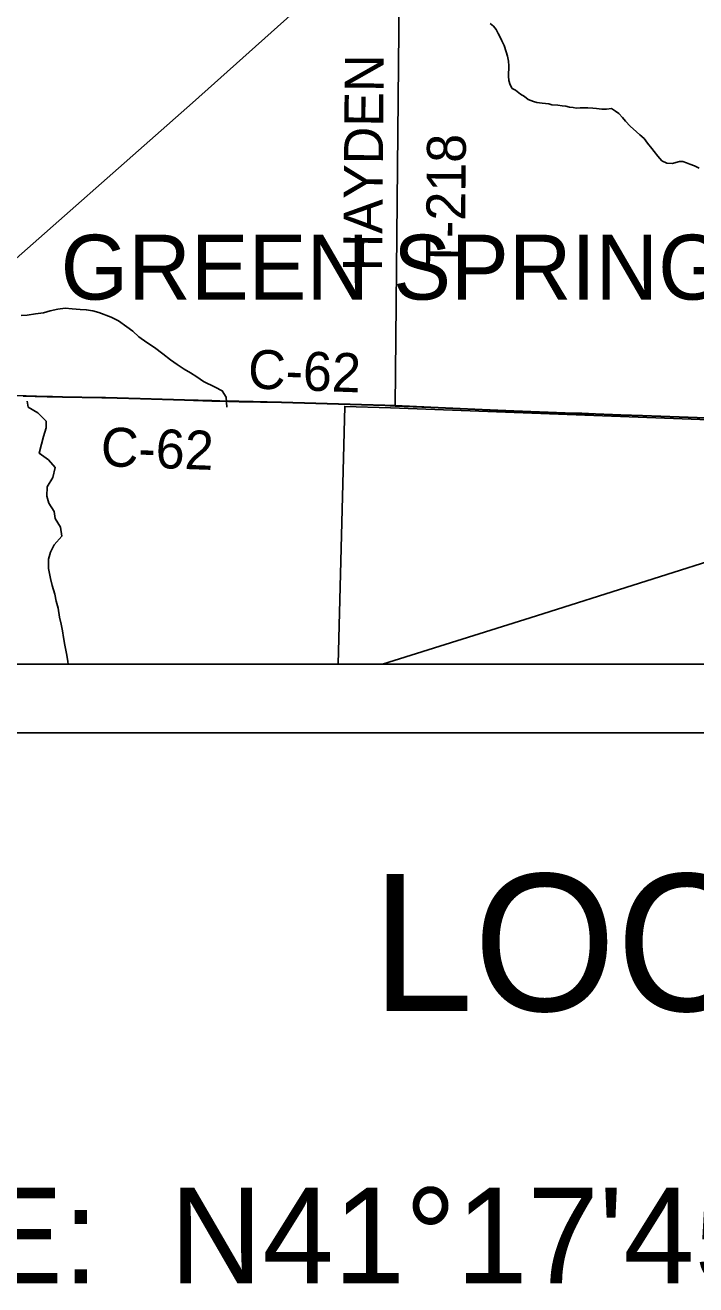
# Model space of a CAD drawing. Extents: x 0 to 34, y 0 to 22.
# Drawn here: x 3.921 to 4.9, y 13.194 to 15.033 of the extents above; entities that cross this region are included whole.
import ezdxf

# ---------------------------------------------------------------- set-up
doc = ezdxf.new("R2010")
doc.units = 0
for name, color, linetype in [('GM_X_Corporation_Text', 7, 'Continuous'), ('GM_X_County_Road', 7, 'Continuous'), ('GM_X_County_Road_Text', 7, 'Continuous'), ('GM_X_Minor_River', 7, 'Continuous'), ('GM_X_Rail_Line', 7, 'Continuous'), ('GM_X_Township', 7, 'Continuous'), ('GM_X_Township_Road', 7, 'Continuous'), ('GM_X_Township_Road_Text', 7, 'Continuous'), ('GM_X_Unincorporated', 7, 'Continuous'), ('SH_Cut_Line', 7, 'Continuous'), ('SH_Data', 7, 'Continuous'), ('SH_Text', 7, 'Continuous')]:
    doc.layers.add(name, color=color, linetype=linetype)

msp = doc.modelspace()

# ---------------------------------------------------------------- linework, layer by layer
at = {"layer": 'GM_X_County_Road'}
for points in [[(3.9178, 14.4915), (3.9531, 14.4905), (3.9611, 14.4904), (3.9621, 14.4903)], [(3.9621, 14.4903), (3.9754, 14.49), (4.0326, 14.4889)], [(4.0326, 14.4889), (4.0382, 14.4888), (4.0891, 14.4874), (4.1537, 14.4857), (4.1935, 14.4844), (4.2177, 14.4836), (4.2333, 14.4834), (4.2954, 14.4821), (4.4122, 14.4789), (4.4464, 14.4777), (4.4614, 14.477)], [(4.4614, 14.477), (4.5134, 14.4747), (4.5886, 14.4714), (4.6345, 14.4693), (4.7097, 14.4664), (4.7339, 14.4658), (4.7538, 14.4651), (4.7911, 14.4638), (4.8227, 14.4626), (4.8891, 14.4601), (4.9289, 14.4587)]]:
    msp.add_lwpolyline(points, dxfattribs=at)
at = {"layer": 'GM_X_Minor_River'}
for points in [[(4.5997, 15.0354), (4.605, 15.0316), (4.6087, 15.027), (4.6117, 15.0209), (4.615, 15.0148), (4.6169, 15.0102), (4.6202, 15.0033), (4.6232, 14.9942), (4.6254, 14.9881), (4.6268, 14.9808), (4.6271, 14.974), (4.6269, 14.9588), (4.6272, 14.9524), (4.6291, 14.9463), (4.632, 14.9409), (4.6369, 14.9382), (4.6441, 14.9324), (4.6501, 14.929), (4.6554, 14.9247), (4.6633, 14.9216), (4.6682, 14.9204), (4.6758, 14.9192), (4.6856, 14.9183), (4.6902, 14.9171), (4.6989, 14.9163), (4.7049, 14.9155), (4.7106, 14.9147), (4.7159, 14.9135), (4.7209, 14.913), (4.7254, 14.9122), (4.7315, 14.9125), (4.7425, 14.9124), (4.7497, 14.912), (4.755, 14.9115), (4.7629, 14.9107), (4.7698, 14.9106), (4.777, 14.9113), (4.783, 14.9074), (4.7879, 14.9043), (4.7931, 14.8986), (4.7976, 14.8928), (4.8044, 14.8859), (4.8138, 14.8775), (4.8186, 14.8733), (4.8246, 14.8675), (4.8299, 14.861), (4.8359, 14.8533), (4.8396, 14.8487), (4.8448, 14.8418), (4.8508, 14.8353), (4.858, 14.8318), (4.8663, 14.8314), (4.8709, 14.8325), (4.8766, 14.8339), (4.8812, 14.8339), (4.8868, 14.8323), (4.8914, 14.8303), (4.8985, 14.8276), (4.9053, 14.8245)], [(3.9148, 14.6092), (3.9239, 14.6099), (3.9357, 14.6117), (3.9478, 14.6131), (3.9573, 14.616), (3.9684, 14.6185), (3.979, 14.6199), (3.9896, 14.6191), (4.001, 14.6182), (4.0101, 14.6177), (4.0195, 14.6161), (4.0282, 14.6137), (4.0464, 14.6067), (4.0573, 14.6013), (4.0693, 14.5928), (4.078, 14.5862), (4.087, 14.5782), (4.0983, 14.5697), (4.1096, 14.5627), (4.122, 14.5531), (4.1333, 14.5443), (4.1427, 14.5377), (4.1528, 14.5311)], [(4.1528, 14.5311), (4.1623, 14.5257), (4.1717, 14.5199), (4.1811, 14.513), (4.1984, 14.5045), (4.2086, 14.4994), (4.2142, 14.4902), (4.2155, 14.4756)], [(3.9236, 14.4841), (3.925, 14.4755), (3.9393, 14.4671), (3.9513, 14.4549), (3.9516, 14.445), (3.9478, 14.4325), (3.9447, 14.4212), (3.9412, 14.4083), (3.9548, 14.3987), (3.9645, 14.3873), (3.961, 14.3729), (3.953, 14.3593), (3.9525, 14.3453), (3.9555, 14.335), (3.963, 14.3232), (3.9648, 14.3126), (3.9723, 14.3004), (3.9745, 14.2871), (3.9634, 14.2743), (3.9577, 14.2637), (3.955, 14.2535), (3.9549, 14.2398), (3.9578, 14.2254), (3.9604, 14.2151), (3.9641, 14.2022), (3.9663, 14.1923), (3.9689, 14.1817), (3.9711, 14.1688), (3.9733, 14.1585), (3.9751, 14.1487), (3.9769, 14.1392), (3.9788, 14.1278), (3.9817, 14.1133), (3.9832, 14.1039), (3.9838, 14.1)]]:
    msp.add_lwpolyline(points, dxfattribs=at)
at = {"layer": 'GM_X_Rail_Line'}
for points in [[(3.6815, 14.4919), (3.8612, 14.6519), (4.1651, 14.9197), (4.4686, 15.1913), (4.7768, 15.471), (5.1412, 15.8006), (5.4601, 16.0872), (6.2018, 16.7592), (6.7493, 17.2493), (7.0065, 17.4955), (7.1712, 17.6375), (7.3789, 17.8309), (7.4524, 17.8921)], [(4.4429, 14.1), (4.6674, 14.1708), (4.9682, 14.2663), (5.0408, 14.2892), (5.2166, 14.345), (5.505, 14.4351)]]:
    msp.add_lwpolyline(points, dxfattribs=at)
at = {"layer": 'GM_X_Township'}
msp.add_lwpolyline([(4.9287, 14.4592), (4.8889, 14.4607), (4.8225, 14.4631), (4.7908, 14.4643), (4.7536, 14.4657), (4.7337, 14.4664), (4.7095, 14.467), (4.6343, 14.4699), (4.5883, 14.472), (4.5132, 14.4753), (4.4612, 14.4776), (4.4461, 14.4782), (4.412, 14.4795), (4.2952, 14.4826), (4.233, 14.484), (4.2175, 14.4841), (4.1932, 14.4849), (4.1535, 14.4862), (4.0889, 14.488), (4.0379, 14.4893), (4.0324, 14.4894), (3.9752, 14.4906), (3.9609, 14.4909), (3.9528, 14.4911), (3.8754, 14.4932)], dxfattribs=at)
at = {"layer": 'GM_X_Township_Road'}
msp.add_line((4.4614, 14.477), (4.4706, 15.4769), dxfattribs=at)
for points in [[(4.9287, 14.4592), (4.8889, 14.4607), (4.8225, 14.4631), (4.7908, 14.4643), (4.7536, 14.4657), (4.7337, 14.4664), (4.7095, 14.467), (4.6343, 14.4699), (4.5883, 14.472), (4.5132, 14.4753), (4.4612, 14.4776), (4.4461, 14.4782), (4.412, 14.4795), (4.2952, 14.4826), (4.233, 14.484), (4.2175, 14.4841), (4.1932, 14.4849), (4.1535, 14.4862), (4.0889, 14.488), (4.0379, 14.4893), (4.0324, 14.4894), (3.9752, 14.4906), (3.9609, 14.4909), (3.9528, 14.4911), (3.8754, 14.4932)], [(2.3817, 14.1), (8.4746, 14.1)]]:
    msp.add_lwpolyline(points, dxfattribs=at)
at = {"layer": 'GM_X_Unincorporated'}
msp.add_lwpolyline([(4.378, 14.1), (5.4154, 14.1), (5.4227, 14.4377), (4.4544, 14.4745), (4.3875, 14.4764)], close=True, dxfattribs=at)
at = {"layer": 'SH_Cut_Line'}
for points in [[(4.9287, 14.4592), (4.8889, 14.4607), (4.8225, 14.4631), (4.7908, 14.4643), (4.7536, 14.4657), (4.7337, 14.4664), (4.7095, 14.467), (4.6343, 14.4699), (4.5883, 14.472), (4.5132, 14.4753), (4.4612, 14.4776), (4.4461, 14.4782), (4.412, 14.4795), (4.2952, 14.4826), (4.233, 14.484), (4.2175, 14.4841), (4.1932, 14.4849), (4.1535, 14.4862), (4.0889, 14.488), (4.0379, 14.4893), (4.0324, 14.4894), (3.9752, 14.4906), (3.9609, 14.4909), (3.9528, 14.4911), (3.8754, 14.4932)], [(3.8754, 14.4932), (3.9528, 14.4911), (3.9609, 14.4909), (3.9752, 14.4906), (4.0324, 14.4894), (4.0379, 14.4893), (4.0889, 14.488), (4.1535, 14.4862), (4.1932, 14.4849), (4.2175, 14.4841), (4.233, 14.484), (4.2952, 14.4826), (4.412, 14.4795), (4.4461, 14.4782), (4.4612, 14.4776), (4.5132, 14.4753), (4.5883, 14.472), (4.6343, 14.4699), (4.7095, 14.467), (4.7337, 14.4664), (4.7536, 14.4657), (4.7908, 14.4643), (4.8225, 14.4631), (4.8889, 14.4607), (4.9287, 14.4592)], [(2.1, 14.1), (8.9, 14.1)]]:
    msp.add_lwpolyline(points, dxfattribs=at)
at = {"layer": 'SH_Data'}
for p, q in [((2.1, 14.1), (8.9, 14.1)), ((2, 14), (9, 14))]:
    msp.add_line(p, q, dxfattribs=at)

# ---------------------------------------------------------------- texts
at = {"layer": 'GM_X_Corporation_Text'}
msp.add_text('GREEN SPRINGS', height=0.094697, rotation=0, dxfattribs=at).set_placement((3.9727, 14.6325))
at = {"layer": 'GM_X_County_Road_Text'}
for rotation, p in [(357.9065, (4.2455, 14.5029)), (358.0036, (4.0306, 14.3894))]:
    msp.add_text('C-62', height=0.05682, rotation=rotation, dxfattribs=at).set_placement(p)
at = {"layer": 'GM_X_Township_Road_Text'}
for s, rotation, p in [('HAYDEN', 89.512, (4.4419, 14.6736)), ('T-218', 89.4386, (4.5627, 14.6758))]:
    msp.add_text(s, height=0.05682, rotation=rotation, dxfattribs=at).set_placement(p)
at = {"layer": 'SH_Text'}
for s, height, p in [('LOCATION MAP', 0.2, (4.4269, 13.5937)), ('LATITUDE:  N41°17\'45.81"   LONGITUDE:  W83°03\'06.42"', 0.14, (3.071, 13.1958))]:
    msp.add_text(s, height=height, dxfattribs=at).set_placement(p)

doc.saveas('drawing.dxf')
